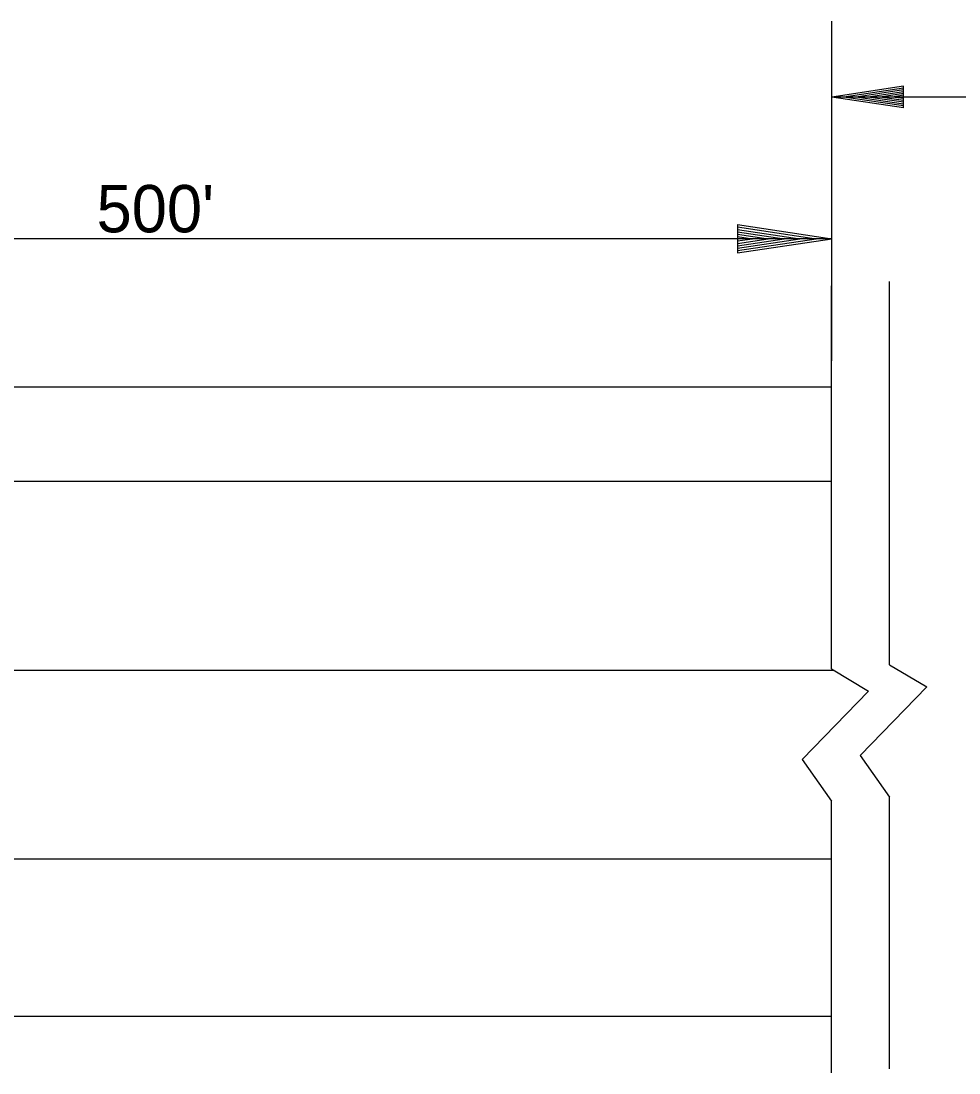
# Model space of a CAD drawing. Extents: x 913 to 1207, y 319 to 519.
# Drawn here: x 1013.55 to 1037.35, y 412.19 to 438.87 of the extents above; entities that cross this region are included whole.
import ezdxf

# ---------------------------------------------------------------- set-up
doc = ezdxf.new("R2010")
doc.units = 0
doc.layers.add('R_Draft', color=7, linetype='Continuous')

msp = doc.modelspace()

# ---------------------------------------------------------------- linework, layer by layer
at = {"layer": 'R_Draft'}
for p, q in [((1034.123, 430.253), (1034.123, 438.871)), ((1035.936, 437.217), (1034.123, 436.945)), ((1035.936, 437.172), (1034.426, 436.945)), ((1035.936, 437.126), (1034.738, 436.945)), ((1035.936, 437.08), (1035.039, 436.945)), ((1035.936, 437.034), (1035.347, 436.945)), ((1035.936, 436.988), (1035.65, 436.945)), ((1035.936, 436.673), (1035.936, 437.217)), ((1075.269, 436.945), (1034.123, 436.945)), ((1035.936, 436.673), (1034.123, 436.945)), ((1035.936, 436.719), (1034.426, 436.945)), ((1035.936, 436.765), (1034.738, 436.945)), ((1035.936, 436.81), (1035.039, 436.945)), ((1035.936, 436.857), (1035.347, 436.945)), ((1035.936, 436.903), (1035.65, 436.945)), ((1031.729, 433.709), (1034.123, 433.35)), ((1031.729, 433.709), (1031.729, 432.991)), ((1031.729, 433.649), (1033.723, 433.35)), ((1031.729, 433.589), (1033.311, 433.35)), ((1031.729, 433.529), (1032.912, 433.35)), ((1034.123, 433.35), (1000.416, 433.35)), ((1031.729, 433.466), (1032.507, 433.35)), ((1031.729, 433.406), (1032.107, 433.35)), ((1031.729, 432.991), (1034.123, 433.35)), ((1031.729, 433.233), (1032.507, 433.35)), ((1031.729, 433.112), (1033.311, 433.35)), ((1031.729, 433.051), (1033.723, 433.35)), ((1031.729, 433.171), (1032.912, 433.35)), ((1031.729, 433.294), (1032.107, 433.35)), ((1035.582, 422.547), (1035.582, 432.264)), ((1034.109, 422.442), (1034.109, 432.159)), ((927.658, 429.592), (1014.46, 429.592)), ((1014.46, 429.592), (1034.109, 429.592)), ((927.658, 427.199), (1014.46, 427.199)), ((1014.46, 427.199), (1034.109, 427.199)), ((927.658, 422.411), (1014.46, 422.411)), ((1014.46, 422.411), (1034.16, 422.411)), ((1035.582, 412.3), (1035.582, 419.19)), ((1034.109, 412.194), (1034.109, 419.085)), ((927.658, 417.623), (1014.46, 417.623)), ((1014.46, 417.623), (1034.109, 417.623)), ((927.658, 413.633), (1014.46, 413.633)), ((1014.46, 413.633), (1034.109, 413.633))]:
    msp.add_line(p, q, dxfattribs=at)
for points in [[(1034.109, 422.442), (1035.052, 421.879), (1033.368, 420.14), (1034.109, 419.085)], [(1035.582, 422.547), (1036.526, 421.985), (1034.841, 420.246), (1035.582, 419.19)]]:
    msp.add_lwpolyline(points, dxfattribs=at)

# ---------------------------------------------------------------- texts
msp.add_text("500'", height=1.2, rotation=360, dxfattribs=at).set_placement((1015.465, 433.513))

doc.saveas('drawing.dxf')
